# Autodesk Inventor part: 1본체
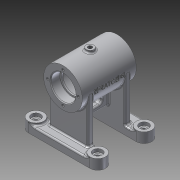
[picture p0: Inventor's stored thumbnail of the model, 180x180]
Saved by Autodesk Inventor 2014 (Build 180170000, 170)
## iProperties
Created: 2015-11
Part Number: 1본체
Material: 알루미늄 6061
Document SubType Name: Modeling
Designer: SEC
Density: 2.71 g/cm^3
Appearance: 알루미늄 - 평지
Mass: 359.113 g
Surface Area: 459.582 cm^2
Volume: 132.514 cm^3
Author: SEC
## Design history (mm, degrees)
sketch "스케치1"
  geometry: L1 (0, 10)-(80, 10); L2 (0, -10)-(80, -10); A1 r 10 centre (0, 0) between (0, 10) and (0, -10); A2 r 10 centre (80, 0) between (80, -10) and (80, 10); 1 further point
  constraints: 5 end point, 4 point on circle, 4 tangent, 2 centre point, 1 coincident, 1 horizontal alignment, 1 parallel
  dimensions: "d2" = 80 distance of L1.start L1.end; "d6" = 10 radius of A1
extrude "돌출1" new body sketch "스케치1" distance "d7" = 10; taper "d8" = 0 deg
node "작업 평면1"
sketch "스케치2"
  geometry: L1 (80, 0)-(0, 0) reference; L2 (80, 80)-(0, 80) reference; L3 (0, 60)-(80, 60) reference; C1 r 10 at (80, 10); C2 r 10 at (0, 10); A1 r 10 centre (80, 10) between (80, 0) and (80, 20) reference; A2 r 10 centre (0, 10) between (0, 20) and (0, 0) reference; A3 r 10 centre (0, 70) between (0, 80) and (0, 60) reference; A4 r 10 centre (80, 70) between (80, 60) and (80, 80) reference; 3 further points
  constraints: 4 coincident, 2 centre point, 2 vertical alignment, 1 concentric, 1 tangent, 4 other
extrude "돌출2" join sketch "스케치2" distance "d10" = 3; taper "d11" = 0 deg
node "작업 평면2"
sketch "스케치3"
  geometry: L1 (-50, 13)-(-70, 13) reference; L2 (-70, 0)-(-50, 0) reference; L3 (-70, 0)-(-70, 10) reference; L4 (-50, 10)-(-70, 10) reference; L5 (-50, 0)-(-50, 10) reference; L6 (10, 13)-(-10, 13) reference; L7 (10, 0)-(-10, 0) reference; L8 (-10, 0)-(-10, 10) reference; L9 (10, 10)-(-10, 10) reference; L10 (10, 0)-(10, 10) reference; L11 (-65, 68)-(5, 68); L12 (-65, 84)-(-65, 93); L13 (-65, 93)-(5, 93); L14 (5, 93)-(5, 84); L15 (-65, 84)-(-53, 84); L16 (-53, 84)-(-53, 82); L17 (-53, 82)-(-51, 82); L18 (-51, 82)-(-51, 89); L19 (-51, 89)-(-9, 89); L20 (-9, 89)-(-9, 82); L21 (-9, 82)-(-7, 82); L22 (-7, 82)-(-7, 84); L23 (-7, 84)-(5, 84); 1 further point
  constraints: 26 end point, 7 parallel, 6 perpendicular, 2 point on line, 1 collinear
  dimensions: "d13" = 70 distance of L11.start L11.end; "d14" = 68 distance from line of L7 L11.end; "d15" = 5 distance from line of L11.start L3; "d16" = 32 diameter of L23 L11; "d17" = 28 diameter of L21 L11; "d18" = 42 diameter of L19 L11; "d19" = 28 diameter of L17 L11; "d20" = 32 diameter of L15 L11; "d21" = 50 diameter of L13 L11; "d22" = 42 distance of L18.end L19.end; "d23" = 12 distance of L22.end L14.end; "d24" = 12 distance of L12.start L15.end
revolve "회전1" sketch "스케치3" stored, may be unused: angle "d25" = 90 deg
sketch "스케치4"
  geometry: L1 (80, 60)-(0, 60) reference; L2 (0, 40)-(80, 40) reference; L3 (80, -20)-(0, -20) reference; L4 (0, 0)-(80, 0) reference; L5 (15, 40)-(65, 40); L6 (65, 40)-(65, 48); L7 (65, 48)-(15, 48); L8 (15, 48)-(15, 40); L9 (15, 0)-(65, 0); L10 (65, 0)-(65, -8); L11 (65, -8)-(15, -8); L12 (15, -8)-(15, 0); A1 r 10 centre (80, 50) between (80, 40) and (80, 60) reference; A2 r 10 centre (0, 50) between (0, 60) and (0, 40) reference; A3 r 10 centre (0, -10) between (0, 0) and (0, -20) reference; A4 r 10 centre (80, -10) between (80, -20) and (80, 0) reference; 1 further point
  constraints: 16 end point, 4 parallel, 2 horizontal, 2 perpendicular, 2 point on line, 1 collinear
  dimensions: "d26" = 8 distance of L5.end L6.end; "d27" = 8 distance of L9.end L10.end; "d28" = 50 distance of L6.end L7.end; "d29" = 50 distance of L10.end L11.end; "d30" = 15 distance from line of L8 point (0, 50)
extrude "돌출3" join sketch "스케치4" stored distance "d31" = 3; taper "d32" = 0 deg
node "작업 평면3"
sketch "스케치5"
  geometry: L1 (65, 75)-(15, 75) reference; L2 (65, 12)-(65, 20) reference; L3 (65, 12)-(15, 12) reference; L4 (15, 12)-(15, 20) reference; L5 (15, 20)-(65, 20) reference; L6 (65, 5)-(15, 5) reference; L7 (65, 60)-(65, 68) reference; L8 (65, 60)-(15, 60) reference; L9 (15, 60)-(15, 68) reference; L10 (15, 68)-(65, 68) reference; L11 (44, 12)-(36, 12); L12 (36, 12)-(36, 60); L13 (36, 60)-(44, 60); L14 (44, 60)-(44, 12); 1 further point
  constraints: 8 end point, 2 parallel, 2 point on line, 1 horizontal, 1 perpendicular
  dimensions: "d34" = 8 distance of L11.start L11.end; "d35" = 21 distance between parallel lines of L14 L2
extrude "돌출4" join sketch "스케치5" stored distance "d36" = 3; taper "d37" = 0 deg
sketch "스케치6"
  geometry: L1 (0, 40)-(0, 0) reference; L2 (-10, 12)-(-10, 28); L3 (-13.5, 12)-(-13.5, 28); L4 (-6.5, 28)-(-6.5, 12); L5 (23, 60)-(23, 40) reference; L6 (-20, -15)-(-70, -15) reference; A1 r 3.5 centre (-10, 12) between (-13.5, 12) and (-6.5, 12); A2 r 3.5 centre (-10, 28) between (-6.5, 28) and (-13.5, 28); 2 further points
  constraints: 8 end point, 4 point on circle, 4 tangent, 2 centre point, 2 parallel, 1 midpoint
  dimensions: "d38" = 3.5 radius of A2; "d39" = 33 distance from line of point (-10, 20) L5; "d40" = 23 dimension on A2 A1; "d41" = 35 distance from line of point (-10, 20) L6
extrude "돌출5" cut sketch "스케치6" stored distance "d42" = 3; taper "d43" = 0 deg
node "작업 평면4"
sketch "스케치7"
  geometry: L1 (-15, -65)-(-65, -65) reference; L2 (-36, -10)-(-36, -50) reference; L3 (-36, -50)-(-15, -50) reference; L4 (-15, -58)-(-15, -50) reference; L5 (-15, -58)-(-65, -58) reference; L6 (-65, -58)-(-65, -50) reference; L7 (-65, -50)-(-44, -50) reference; L8 (-44, -50)-(-44, -10) reference; L9 (-44, -10)-(-65, -10) reference; L10 (-65, -10)-(-65, -2) reference; L11 (-65, -2)-(-15, -2) reference; L12 (-15, -10)-(-15, -2) reference; L13 (-15, -10)-(-36, -10) reference; L14 (-15, 5)-(-65, 5) reference; C1 r 5 at (-40, -30); 3 further points
  constraints: 2 midpoint, 1 centre point, 1 horizontal alignment, 1 vertical alignment
  dimensions: "d45" = 10 diameter of C1
extrude "돌출6" join sketch "스케치7" stored distance "d46" = 3; taper "d47" = 0 deg
hole "구멍1" diameter "d50" = 5.188; stored, may be unused: countersink angle "d54" = 90 deg, drill point angle "d56" = 118 deg; dims "d48" = 10, "d49" = 10, "d51" = 6, "d52" = 4, "d53" = 2, "d55" = 8
node "작업 평면9"
  node "작업 평면8"
sketch "스케치9"
  geometry: L1 (-35, -25)-(-35, 25) reference; L2 (20, -8.875)-(-20, -8.875) reference; L3 (-20, -8.875)-(-20, 21.651) reference; L4 (-28, 21.651)-(-20, 21.651) reference; L5 (-28, 21.651)-(-28, -21.651) reference; L6 (-28, -21.651)-(-20, -21.651) reference; L7 (-20, -21.651)-(-20, -15.803) reference; L8 (-20, -15.803)-(20, -15.803) reference; L9 (20, -15.803)-(20, -21.651) reference; L10 (20, -21.651)-(28, -21.651) reference; L11 (28, -21.651)-(28, 21.651) reference; L12 (20, 21.651)-(28, 21.651) reference; L13 (20, 21.651)-(20, -8.875) reference; L14 (35, -25)-(35, 25) reference; L15 (-35, 25)-(35, 25) reference; C1 r 6 at (0, 0); 3 further points
  constraints: 1 centre point, 1 horizontal alignment, 1 midpoint, 1 vertical alignment, 1 other
  dimensions: "d60" = 12 diameter of C1
extrude "돌출7" join sketch "스케치9" stored distance "d61" = 3; taper "d62" = 0 deg
hole "구멍2" diameter "d65" = 5.188; stored, may be unused: countersink angle "d69" = 90 deg, drill point angle "d71" = 118 deg; dims "d63" = 10, "d64" = 10, "d66" = 6, "d67" = 4, "d68" = 2, "d70" = 8
hole "구멍3" diameter "d74" = 6; stored, may be unused: countersink angle "d78" = 90 deg, drill point angle "d80" = 118 deg; dims "d72" = 10, "d73" = 10, "d75" = 6, "d76" = 4, "d77" = 2, "d79" = 8
hole "구멍4" diameter "d83" = 6; stored, may be unused: countersink angle "d87" = 90 deg, drill point angle "d89" = 118 deg; dims "d81" = 10, "d82" = 10, "d84" = 6, "d85" = 4, "d86" = 2, "d88" = 8
hole "구멍5" diameter "d92" = 6; stored, may be unused: countersink angle "d96" = 90 deg, drill point angle "d98" = 118 deg; dims "d90" = 10, "d91" = 10, "d93" = 6, "d94" = 4, "d95" = 2, "d97" = 8
hole "구멍6" diameter "d101" = 6; stored, may be unused: countersink angle "d105" = 90 deg, drill point angle "d107" = 118 deg; dims "d99" = 10, "d100" = 10, "d102" = 6, "d103" = 4, "d104" = 2, "d106" = 8
sketch "스케치10"
  geometry: C1 r 3 at (0, 0) reference; C2 r 10 at (0, 0) reference; C3 r 6 at (0, 0); C4 r 3 at (-80, 0) reference; C5 r 10 at (-80, 0) reference; C6 r 3 at (0, 60) reference; C7 r 10 at (0, 60) reference; C8 r 6 at (0, 60); C9 r 6 at (-80, 60); C10 r 6 at (-80, 0); 1 further point
  constraints: 4 centre point, 4 coincident, 3 equal radius
  dimensions: "d108" = 12 diameter of C8
extrude "돌출8" cut sketch "스케치10" distance "d109" = 4; taper "d110" = 0 deg
node "작업 평면10"
sketch "스케치11"
  geometry: L1 (35, -25)-(35, 25) reference; L2 (40, -68)-(20, -68) reference; L3 (-35, 25)-(35, 25) reference; 3 further points
  constraints: 1 midpoint, 1 vertical alignment, 1 other
  dimensions: "d112" = 25 vertical distance of point (0, 0) L1.end
feature "엠보싱1" sketch "스케치11" dims "d113" = 0.5, "d114" = 0
sketch "스케치12" dims "d115" = 40
  geometry: C1 r 16 at (0, 0) reference; C2 r 25 at (0, 0) reference; 3 further points
  constraints: 2 vertical alignment, 1 coincident, 2 other
hole "구멍7" sketch "스케치12" at (0, 20) diameter "d116" = 3.242; stored, may be unused: countersink angle "d120" = 90 deg, drill point angle "d122" = 118 deg; dims "d117" = 8, "d118" = 4, "d119" = 2, "d121" = 10
node "작업 평면11"
chamfer "모따기1" distance "d127" = 1; stored, may be unused: second distance "d128" = 2, angle "d129" = 45 deg
fillet "모깎기1" dims "d130" = 0.3
fillet "모깎기2" dims "d131" = 3
fillet "모깎기3" dims "d132" = 0.3
chamfer "모따기2" distance "d133" = 1; stored, may be unused: second distance "d134" = 2, angle "d135" = 45 deg
fillet "모깎기4" dims "d136" = 2
fillet "모깎기5" dims "d137" = 2
fillet "모깎기6" dims "d138" = 2
fillet "모깎기7" dims "d139" = 2
fillet "모깎기8" dims "d140" = 2
fillet "모깎기9" dims "d141" = 2
fillet "모깎기10" dims "d142" = 2
fillet "모깎기11" dims "d143" = 2
fillet "모깎기13" dims "d145" = 2
fillet "모깎기15" dims "d147" = 2
fillet "모깎기16" dims "d148" = 2
fillet "모깎기17" dims "d149" = 2
fillet "모깎기18" dims "d150" = 2
node "솔리드1"
mirror "대칭1"
pattern_circular "원형 패턴1" dims angle "d124" = 360 deg
mirror "대칭2"
node "투영된 루프1"
node "투영된 루프2"
node "투영된 루프3"
node "투영된 루프4"
node "투영된 루프5"
node "투영된 루프6"
node "투영된 루프7"
node "작업 평면5"
node "작업 평면6"
node "작업 평면7"
node "투영된 루프9"
node "투영된 루프10"
node "투영된 루프11"
other parameters: "d33" = -23, "d44" = -96, "d57" = 25, "d58" = 60 deg, "d59" = -3, "d126" = -35
